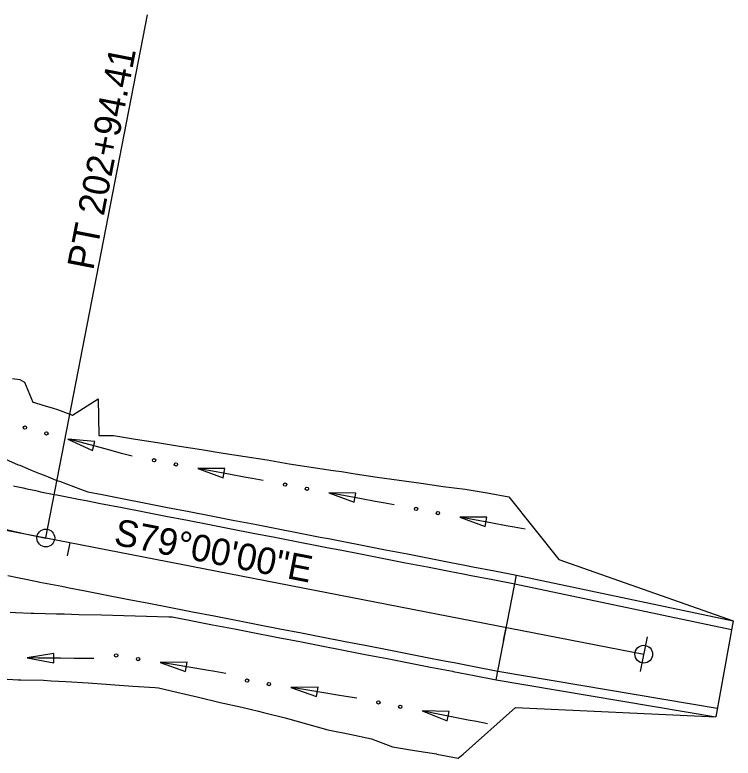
# Model space of a CAD drawing. Extents: x 1556849 to 1559393, y 1802592 to 1804749.
# Drawn here: x 1558530.6 to 1558692.3, y 1804371.3 to 1804538.6 of the extents above; entities that cross this region are included whole.
import ezdxf

# ---------------------------------------------------------------- set-up
doc = ezdxf.new("R2010")
doc.units = 0
for name, color, linetype in [('R_Horz Alg', 7, 'Continuous'), ('R_Horz Alg Annot', 7, 'Continuous'), ('R_Proposed Const Limits_Cut', 7, 'Continuous'), ('R_Proposed Road_Lane', 7, 'Continuous'), ('R_Proposed Road_Shoulder', 7, 'Continuous'), ('R_Water', 7, 'Continuous')]:
    doc.layers.add(name, color=color, linetype=linetype)

msp = doc.modelspace()

# ---------------------------------------------------------------- linework, layer by layer
at = {"layer": 'R_Horz Alg'}
msp.add_line((1558537.6, 1804420.83), (1558672.21, 1804394.66), dxfattribs=at)
msp.add_arc((1558587.29, 1804676.48), 260.44, 226, 259, dxfattribs=at)
at = {"layer": 'R_Horz Alg Annot'}
msp.add_line((1558461.87, 1804435.55), (1558537.6, 1804420.83), dxfattribs=at)
for points in [[(1558537.6, 1804420.83), (1558560.49, 1804538.63)], [(1558542.51, 1804416.82), (1558543.08, 1804419.76)], [(1558640.67, 1804397.74), (1558641.25, 1804400.68)], [(1558672.97, 1804398.59), (1558671.44, 1804390.74)]]:
    msp.add_lwpolyline(points, dxfattribs=at)
for centre in [(1558537.6, 1804420.83), (1558672.21, 1804394.66)]:
    msp.add_circle(centre, 2, dxfattribs=at)
at = {"layer": 'R_Proposed Const Limits_Cut'}
for points in [[(1558530.1, 1804456.73), (1558531.76, 1804456.54), (1558532.83, 1804455.91), (1558534.7, 1804451.41), (1558535.02, 1804451.32), (1558536.72, 1804450.82), (1558537.48, 1804450.6), (1558539.29, 1804450.07), (1558540.27, 1804449.76), (1558543.01, 1804448.7), (1558543.58, 1804448.5), (1558549.39, 1804452.19), (1558549.56, 1804443.91), (1558552.87, 1804443.9), (1558557.81, 1804443.11), (1558562.75, 1804442.33), (1558567.69, 1804441.53), (1558572.63, 1804440.72), (1558577.56, 1804439.92), (1558582.51, 1804439.15), (1558587.46, 1804438.41), (1558592.38, 1804437.54), (1558597.33, 1804436.77), (1558602.28, 1804436.06), (1558604.17, 1804435.78), (1558607.22, 1804435.25), (1558612.17, 1804434.51), (1558617.13, 1804433.83), (1558622.09, 1804433.14), (1558627.04, 1804432.43), (1558632.01, 1804431.79), (1558635.14, 1804431.3), (1558636.96, 1804431.01), (1558641.87, 1804430.1), (1558653.12, 1804416.01), (1558692.33, 1804402.2)], [(1558527.69, 1804389.1), (1558531.39, 1804388.9), (1558531.99, 1804388.89), (1558537.06, 1804388.79), (1558538.83, 1804388.7), (1558542.11, 1804388.53), (1558547.13, 1804388.18), (1558552.15, 1804387.81), (1558557.18, 1804387.44), (1558562.21, 1804387.15), (1558562.97, 1804387.11), (1558567.11, 1804386.13), (1558571.97, 1804384.95), (1558576.84, 1804383.79), (1558581.73, 1804382.72), (1558585.51, 1804381.82), (1558586.59, 1804381.55), (1558591.45, 1804380.34), (1558596.27, 1804378.95), (1558601.12, 1804377.66), (1558606.01, 1804376.63), (1558610.9, 1804375.57), (1558615.65, 1804373.8), (1558620.58, 1804372.95), (1558625.52, 1804372.2), (1558625.66, 1804372.17), (1558630.43, 1804371.26), (1558631.53, 1804372.18)], [(1558631.53, 1804372.18), (1558643.33, 1804382.67), (1558688.41, 1804380.55)]]:
    msp.add_lwpolyline(points, dxfattribs=at)
at = {"layer": 'R_Proposed Road_Lane'}
for p, q in [((1558638.96, 1804388.9), (1558643.54, 1804412.46)), ((1558643.16, 1804410.5), (1558691.98, 1804400.23)), ((1558692.33, 1804402.2), (1558688.41, 1804380.55)), ((1558639.34, 1804390.87), (1558688.77, 1804382.52))]:
    msp.add_line(p, q, dxfattribs=at)
for points in [[(1558530.31, 1804432.61), (1558530.66, 1804432.53), (1558532.53, 1804432.11), (1558533.36, 1804431.92), (1558535.35, 1804431.49), (1558536.43, 1804431.26), (1558539.51, 1804430.65), (1558540.08, 1804430.53), (1558544.99, 1804429.58), (1558546.71, 1804429.25), (1558549.9, 1804428.63), (1558554.81, 1804427.67), (1558559.72, 1804426.72), (1558564.63, 1804425.76), (1558569.53, 1804424.81), (1558574.44, 1804423.86), (1558579.35, 1804422.9), (1558584.26, 1804421.95), (1558589.17, 1804420.99), (1558594.07, 1804420.04), (1558598.98, 1804419.09), (1558600.86, 1804418.72), (1558603.89, 1804418.13), (1558608.8, 1804417.18), (1558613.71, 1804416.22), (1558618.61, 1804415.27), (1558623.52, 1804414.31), (1558628.43, 1804413.36), (1558631.53, 1804412.76), (1558633.34, 1804412.41), (1558638.25, 1804411.45), (1558643.16, 1804410.5)], [(1558529.06, 1804412.39), (1558531.2, 1804411.93), (1558532.37, 1804411.68), (1558535.69, 1804411.01), (1558536.27, 1804410.9), (1558541.18, 1804409.95), (1558542.89, 1804409.61), (1558546.08, 1804408.99), (1558550.99, 1804408.04), (1558555.9, 1804407.08), (1558560.81, 1804406.13), (1558565.72, 1804405.18), (1558570.63, 1804404.22), (1558575.53, 1804403.27), (1558580.44, 1804402.31), (1558585.35, 1804401.36), (1558590.26, 1804400.41), (1558595.17, 1804399.45), (1558597.04, 1804399.09), (1558600.07, 1804398.5), (1558604.98, 1804397.54), (1558609.89, 1804396.59), (1558614.8, 1804395.64), (1558619.71, 1804394.68), (1558624.61, 1804393.73), (1558627.72, 1804393.13), (1558629.52, 1804392.77), (1558634.43, 1804391.82), (1558639.34, 1804390.87)]]:
    msp.add_lwpolyline(points, dxfattribs=at)
at = {"layer": 'R_Proposed Road_Shoulder'}
for p, q in [((1558643.54, 1804412.46), (1558692.33, 1804402.2)), ((1558638.96, 1804388.9), (1558688.41, 1804380.55))]:
    msp.add_line(p, q, dxfattribs=at)
for points in [[(1558528.55, 1804438.59), (1558531.41, 1804437.34), (1558531.74, 1804437.2), (1558533.51, 1804436.46), (1558534.29, 1804436.13), (1558536.17, 1804435.36), (1558537.2, 1804434.95), (1558540.12, 1804433.81), (1558540.68, 1804433.6), (1558545.43, 1804431.83), (1558547.09, 1804431.21), (1558550.28, 1804430.59), (1558555.19, 1804429.63), (1558560.1, 1804428.68), (1558565.01, 1804427.73), (1558569.91, 1804426.77), (1558574.82, 1804425.82), (1558579.73, 1804424.86), (1558584.64, 1804423.91), (1558589.55, 1804422.96), (1558594.46, 1804422), (1558599.36, 1804421.05), (1558601.24, 1804420.68), (1558604.27, 1804420.09), (1558609.18, 1804419.14), (1558614.09, 1804418.19), (1558619, 1804417.23), (1558623.9, 1804416.28), (1558628.81, 1804415.32), (1558631.91, 1804414.72), (1558633.72, 1804414.37), (1558638.63, 1804413.42), (1558643.54, 1804412.46)], [(1558529.55, 1804404.14), (1558530.79, 1804404.08), (1558534.31, 1804403.92), (1558534.91, 1804403.91), (1558539.98, 1804403.77), (1558541.75, 1804403.72), (1558545.04, 1804403.63), (1558550.11, 1804403.5), (1558555.18, 1804403.36), (1558560.24, 1804403.23), (1558565.31, 1804403.09), (1558566.07, 1804403.07), (1558570.24, 1804402.26), (1558575.15, 1804401.31), (1558580.06, 1804400.35), (1558584.97, 1804399.4), (1558588.79, 1804398.66), (1558589.88, 1804398.44), (1558594.78, 1804397.49), (1558599.69, 1804396.54), (1558604.6, 1804395.58), (1558609.51, 1804394.63), (1558614.42, 1804393.67), (1558619.32, 1804392.72), (1558624.23, 1804391.76), (1558629.14, 1804390.81), (1558629.28, 1804390.78), (1558634.05, 1804389.86), (1558638.96, 1804388.9)]]:
    msp.add_lwpolyline(points, dxfattribs=at)
at = {"layer": 'R_Water'}
for p, q in [((1558542.57, 1804443.11), (1558548.09, 1804440.53)), ((1558548.64, 1804442.58), (1558542.57, 1804443.11)), ((1558548.09, 1804440.53), (1558548.64, 1804442.58)), ((1558571.81, 1804436.5), (1558577.51, 1804434.36)), ((1558577.9, 1804436.44), (1558571.81, 1804436.5)), ((1558577.51, 1804434.36), (1558577.9, 1804436.44)), ((1558601.3, 1804431.03), (1558607.01, 1804428.88)), ((1558607.4, 1804430.96), (1558601.3, 1804431.03)), ((1558607.01, 1804428.88), (1558607.4, 1804430.96)), ((1558630.8, 1804425.55), (1558636.5, 1804423.41)), ((1558636.89, 1804425.49), (1558630.8, 1804425.55)), ((1558636.5, 1804423.41), (1558636.89, 1804425.49)), ((1558539.4, 1804394.81), (1558533.39, 1804393.82)), ((1558539.38, 1804392.7), (1558539.4, 1804394.81)), ((1558533.39, 1804393.82), (1558539.38, 1804392.7)), ((1558569.42, 1804392.85), (1558563.32, 1804392.79)), ((1558563.32, 1804392.79), (1558569.07, 1804390.77)), ((1558569.07, 1804390.77), (1558569.42, 1804392.85)), ((1558598.88, 1804387.24), (1558592.79, 1804387.16)), ((1558592.79, 1804387.16), (1558598.54, 1804385.15)), ((1558598.54, 1804385.15), (1558598.88, 1804387.24)), ((1558622.31, 1804381.89), (1558627.99, 1804379.69)), ((1558628.41, 1804381.76), (1558622.31, 1804381.89)), ((1558627.99, 1804379.69), (1558628.41, 1804381.76))]:
    msp.add_line(p, q, dxfattribs=at)
for points in [[(1558557.06, 1804439.23), (1558554.63, 1804439.88), (1558552.81, 1804440.36), (1558549.81, 1804441.17), (1558545, 1804442.46), (1558542.57, 1804443.11)], [(1558586.55, 1804433.75), (1558584.08, 1804434.21), (1558582.23, 1804434.56), (1558579.18, 1804435.13), (1558574.28, 1804436.04), (1558571.81, 1804436.5)], [(1558616.05, 1804428.27), (1558613.57, 1804428.73), (1558611.72, 1804429.08), (1558608.68, 1804429.65), (1558603.78, 1804430.56), (1558601.3, 1804431.03)], [(1558645.55, 1804422.8), (1558643.07, 1804423.26), (1558641.22, 1804423.6), (1558638.17, 1804424.17), (1558633.27, 1804425.09), (1558630.8, 1804425.55)], [(1558548.39, 1804393.66), (1558545.87, 1804393.68), (1558543.99, 1804393.7), (1558540.89, 1804393.74), (1558535.91, 1804393.79), (1558533.39, 1804393.82)], [(1558578.12, 1804390.35), (1558575.64, 1804390.76), (1558573.78, 1804391.06), (1558570.72, 1804391.57), (1558565.81, 1804392.38), (1558563.32, 1804392.79)], [(1558607.6, 1804384.76), (1558605.11, 1804385.16), (1558603.25, 1804385.46), (1558600.19, 1804385.96), (1558595.27, 1804386.76), (1558592.79, 1804387.16)], [(1558637.03, 1804378.98), (1558634.56, 1804379.47), (1558632.71, 1804379.83), (1558629.67, 1804380.44), (1558624.78, 1804381.4), (1558622.31, 1804381.89)]]:
    msp.add_lwpolyline(points, dxfattribs=at)
for centre in [(1558532.89, 1804445.68), (1558537.73, 1804444.38), (1558561.96, 1804438.32), (1558566.88, 1804437.39), (1558591.45, 1804432.84), (1558596.38, 1804431.91), (1558620.95, 1804427.36), (1558625.87, 1804426.44), (1558553.44, 1804394.39), (1558558.38, 1804393.57), (1558582.9, 1804388.73), (1558587.84, 1804387.93), (1558612.48, 1804383.81), (1558617.4, 1804382.83)]:
    msp.add_circle(centre, 0.375, dxfattribs=at)

# ---------------------------------------------------------------- texts
at = {"layer": 'R_Horz Alg Annot'}
for s, rotation, p in [('PT 202+94.41', 79, (1558548.26, 1804480.94)), ('S79%%d00\'00"E', 349, (1558552.7, 1804419.36))]:
    msp.add_text(s, height=6, rotation=rotation, dxfattribs=at).set_placement(p)

doc.saveas('drawing.dxf')
